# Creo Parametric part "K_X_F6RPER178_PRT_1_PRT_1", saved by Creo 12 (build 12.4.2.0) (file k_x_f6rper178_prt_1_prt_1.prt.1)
Units: Custom; MM, KILOGRAM, SECS

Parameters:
  PTC_WM_ITERATION = "0"
  PTC_WM_VERSION = "-.0"
  PTC_WM_LIFECYCLE_STATE = "In Work"
  PTC_WM_LIFECYCLE = "MO_CADDocument"
  PTC_WM_CREATED_BY = "Maximilian Roepper (Z0017RMS: MO)"
  PTC_WM_CREATED_ON = "18-Sep-26 11:36:42 AM"
  PTC_WM_MODIFIED_BY = "Maximilian Roepper (Z0017RMS: MO)"
  PTC_WM_MODIFIED_ON = "18-Sep-26 11:36:46 AM"
  PDMLINKNUMBER = "PDM000071454887"
  PTC_WM_NAME = "k_x_f6rper178_prt_1_prt_1.prt"
  PTC_WM_NUMBER = "PDM000071454887"

Other parameters: WEIGHT, WEIGHT_FACTOR, WEIGHT_ADD, _MASS_TEMP, _DIFF_TEMP, MC_ERRORS, SUPPLIER

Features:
  1. coordinate system
  2. datum plane "PRT_YZ"
  3. datum plane "PRT_XY"
  4. datum plane "PRT_XZ"
  5. coordinate system
  6. datum axis
  7. datum axis
  8. datum axis
  9. coordinate system
  10. imported feature
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
Other named items: PRT, SIEMENS_MO, DRW_VIEW_ORG, PRT_X, PRT_Y, PRT_Z, CS0, ROUGH_GROB

Layers: 00_STD_CSYS-KSYS, 01_STD_PLANES-EBENEN, 02_STD_AXES-ACHSEN, 03_STD_CSYS-KSYS, 24_IMPORT_FEAT-IMPORT_KE

Surfaces: 7 plane, 4 tabulated cylinder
